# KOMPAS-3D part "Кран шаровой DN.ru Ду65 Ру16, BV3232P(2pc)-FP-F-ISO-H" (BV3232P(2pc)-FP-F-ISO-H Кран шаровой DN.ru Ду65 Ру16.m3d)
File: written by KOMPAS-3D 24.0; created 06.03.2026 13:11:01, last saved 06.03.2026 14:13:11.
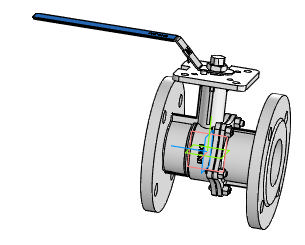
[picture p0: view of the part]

Document properties: Автор: R2D2; Полное имя файла: BV3232P(2pc)-FP-F-ISO-H Кран шаровой DN.ru Ду65 Ру16.cdw

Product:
- Part/product: Кран шаровой DN.ru Ду65 Ру16  | designation BV3232P(2pc)-FP-F-ISO-H
    Масса: 12.04
    Раздел спецификации: Прочие изделия
    Форматы листов документа: A2
    Примечание: D160-22135

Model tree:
1. Операция без истории:2

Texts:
  BV3232P(2pc)-FP-F-ISO-H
